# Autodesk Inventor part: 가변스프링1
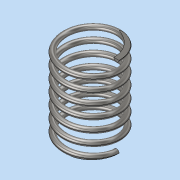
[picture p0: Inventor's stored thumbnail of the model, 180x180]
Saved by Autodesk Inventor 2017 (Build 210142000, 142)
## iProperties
Part Number: 가변스프링1
Material: 스테인레스 스틸
Document SubType Name: Modeling
Designer: MRC
Density: 8 g/cm^3
Appearance: 반연마
Mass: 10.9602 g
Surface Area: 27.6886 cm^2
Volume: 1.37003 cm^3
Author: MRC
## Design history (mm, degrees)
sketch "스케치1"
  geometry: L1 (0, 0)-(10, 0); L2 (10, 0)-(10, 30.358); L3 (10, 30.358)-(0, 30.358); L4 (0, 30.358)-(0, 0); C1 r 1 at (10, 0)
  constraints: 8 end point, 2 parallel, 1 centre point, 1 coincident, 1 horizontal, 1 perpendicular
  dimensions: "d1" = 30.35829 distance of L3.end L1.start (derived); "d2" = 20 diameter of L2 L4; "d3" = 2 diameter of C1
feature "코일1" sketch "스케치1" pitch "d4" = 10; turns "d6" = 7; dims "d5" = 30.35829 (= d1), "d7" = 0, angle "d8" = 90 deg, angle "d9" = 90 deg, "d10" = 0, "d11" = 0
sketch "스케치2"
  geometry: L1 (-20, 30.358)-(20, 30.358); L2 (20, 30.358)-(20, 0); L3 (20, 0)-(-20, 0); L4 (-20, 0)-(-20, 30.358); L5 (0, 30.358)-(0, 0) reference; 2 further points
  constraints: 8 end point, 2 midpoint, 2 parallel, 1 coincident, 1 horizontal, 1 perpendicular
  dimensions: "d12" = 40 distance between parallel lines of L4 L2
extrude "돌출1" sketch "스케치2" stored distance "d13" = 0; taper "d14" = 0 deg
node "솔리드1"
